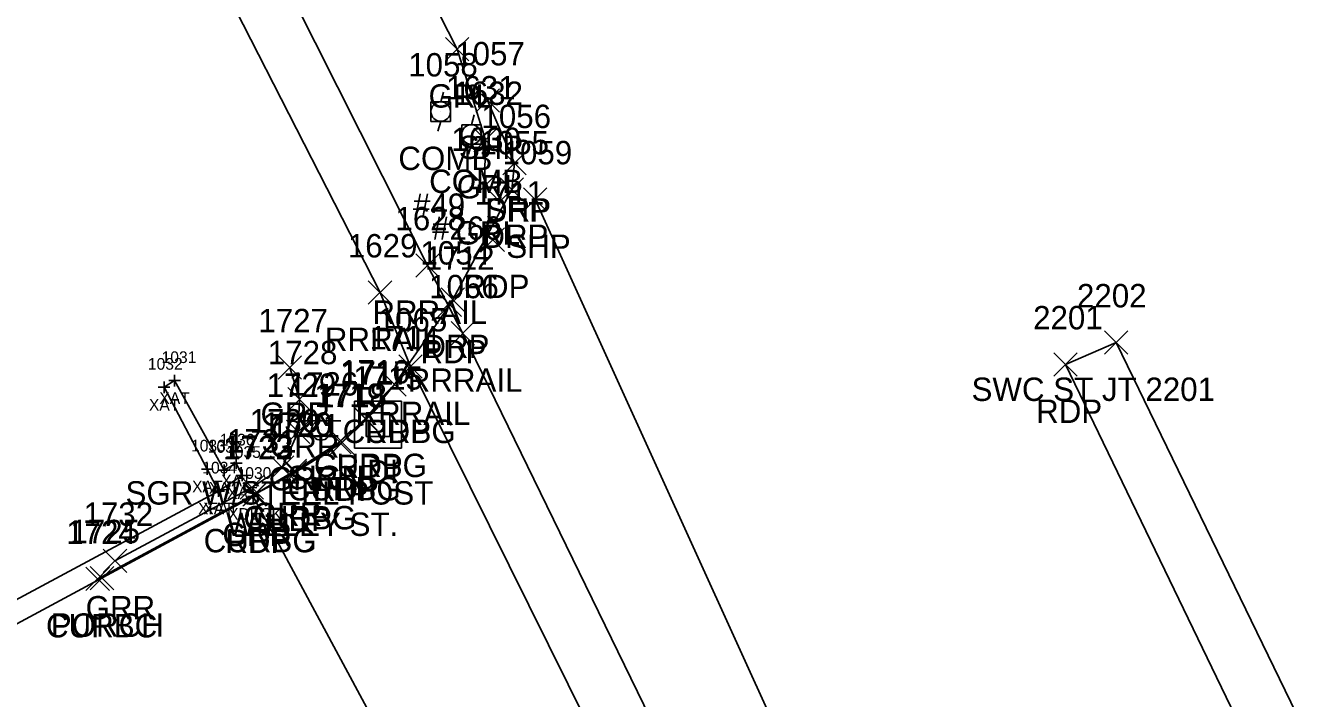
# Model space of a CAD drawing. Extents: x 1635588 to 1637550, y 621583 to 623638.
# Drawn here: x 1636369.1 to 1636479.5, y 623177.4 to 623234.9 of the extents above; entities that cross this region are included whole.
import ezdxf

# ---------------------------------------------------------------- set-up
doc = ezdxf.new("R2010")
doc.units = 0
for name, color, linetype in [('B_A', 7, 'Continuous'), ('B_I', 7, 'Continuous'), ('B_TIC', 7, 'Continuous'), ('BELB', 7, 'Continuous'), ('BF', 7, 'Continuous'), ('BSUBM', 7, 'Continuous'), ('D_A', 7, 'Continuous'), ('D_I', 7, 'Continuous'), ('DS', 7, 'Continuous'), ('L_A', 7, 'Continuous'), ('L_I', 7, 'Continuous'), ('L_TIC', 7, 'Continuous'), ('P_A', 7, 'Continuous'), ('P_I', 7, 'Continuous'), ('P_TIC', 7, 'Continuous'), ('PET', 7, 'Continuous'), ('PSP', 7, 'Continuous'), ('R_A', 7, 'Continuous'), ('R_C', 7, 'Continuous'), ('R_I', 7, 'Continuous'), ('R_TIC', 7, 'Continuous'), ('RC', 7, 'Continuous'), ('RDP', 7, 'Continuous'), ('RGR', 7, 'Continuous'), ('RR', 7, 'Continuous'), ('RSW', 7, 'Continuous'), ('S_A', 7, 'Continuous'), ('S_C', 7, 'Continuous'), ('S_I', 7, 'Continuous'), ('SSGN', 7, 'Continuous'), ('U_A', 7, 'Continuous'), ('U_C', 7, 'Continuous'), ('U_I', 7, 'Continuous'), ('UP', 7, 'Continuous')]:
    doc.layers.add(name, color=color, linetype=linetype)

msp = doc.modelspace()

# ---------------------------------------------------------------- linework, layer by layer
at = {"layer": 'B_TIC'}
for p, q in [((1636380.9, 623204.01), (1636380.98, 623204.01)), ((1636381.79, 623204.58), (1636381.86, 623204.58)), ((1636384.59, 623197.02), (1636384.67, 623197.02)), ((1636387.07, 623197.53), (1636387.15, 623197.53)), ((1636386.02, 623196.91), (1636386.1, 623196.91)), ((1636387.58, 623196.47), (1636387.66, 623196.47)), ((1636385.55, 623195.14), (1636385.63, 623195.14)), ((1636385.55, 623195.14), (1636385.63, 623195.14)), ((1636388.52, 623194.68), (1636388.6, 623194.68))]:
    msp.add_line(p, q, dxfattribs=at)
for points in [[(1636381.79, 623204.08), (1636381.79, 623205.08)], [(1636380.4, 623204.01), (1636381.4, 623204.01)], [(1636380.9, 623203.51), (1636380.9, 623204.51)], [(1636381.29, 623204.58), (1636382.29, 623204.58)], [(1636384.09, 623197.02), (1636385.09, 623197.02)], [(1636384.59, 623196.52), (1636384.59, 623197.52)], [(1636386.02, 623196.41), (1636386.02, 623197.41)], [(1636386.57, 623197.53), (1636387.57, 623197.53)], [(1636387.07, 623197.03), (1636387.07, 623198.03)], [(1636385.52, 623196.91), (1636386.52, 623196.91)], [(1636387.08, 623196.47), (1636388.08, 623196.47)], [(1636387.58, 623195.97), (1636387.58, 623196.97)], [(1636385.05, 623195.14), (1636386.05, 623195.14)], [(1636385.05, 623195.14), (1636386.05, 623195.14)], [(1636385.55, 623194.64), (1636385.55, 623195.64)], [(1636385.55, 623194.64), (1636385.55, 623195.64)], [(1636388.52, 623194.18), (1636388.52, 623195.18)], [(1636388.02, 623194.68), (1636389.02, 623194.68)]]:
    msp.add_lwpolyline(points, dxfattribs=at)
at = {"layer": 'BELB'}
msp.add_lwpolyline([(1636339.78, 623132.09), (1636403.65, 623166.46), (1636403.69, 623166.44), (1636388.52, 623194.68), (1636325.04, 623160.46), (1636339.78, 623132.09)], dxfattribs=at)
at = {"layer": 'BF'}
msp.add_lwpolyline([(1636385.55, 623195.14), (1636325.61, 623162.96)], dxfattribs=at)
at = {"layer": 'BSUBM'}
msp.add_lwpolyline([(1636381.79, 623204.58), (1636380.9, 623204.01), (1636384.59, 623197.02), (1636385.55, 623195.14), (1636387.58, 623196.47), (1636387.07, 623197.53), (1636386.02, 623196.91), (1636381.79, 623204.58)], dxfattribs=at)
at = {"layer": 'DS'}
for p, q in [((1636397.18, 623202.81), (1636401.18, 623202.81)), ((1636397.18, 623198.81), (1636397.18, 623202.81)), ((1636401.18, 623202.81), (1636401.18, 623198.81)), ((1636398.18, 623199.81), (1636398.18, 623201.81)), ((1636398.18, 623201.81), (1636400.18, 623201.81)), ((1636400.18, 623201.81), (1636400.18, 623199.81)), ((1636399.18, 623200.81), (1636399.18, 623200.81)), ((1636399.18, 623200.81), (1636399.18, 623200.81)), ((1636400.18, 623199.81), (1636398.18, 623199.81)), ((1636401.18, 623198.81), (1636397.18, 623198.81))]:
    msp.add_line(p, q, dxfattribs=at)
at = {"layer": 'L_TIC'}
for points in [[(1636374.59, 623186.68), (1636376.59, 623188.68)], [(1636376.59, 623186.68), (1636374.59, 623188.68)]]:
    msp.add_lwpolyline(points, dxfattribs=at)
at = {"layer": 'P_TIC'}
for points in [[(1636407.55, 623227.53), (1636409.55, 623229.53)], [(1636409.55, 623227.53), (1636407.55, 623229.53)], [(1636409.84, 623222.17), (1636411.84, 623224.17)], [(1636411.84, 623222.17), (1636409.84, 623224.17)], [(1636411.61, 623219.07), (1636413.61, 623221.07)], [(1636413.61, 623219.07), (1636411.61, 623221.07)], [(1636407.99, 623215.63), (1636409.99, 623217.63)], [(1636409.99, 623215.63), (1636407.99, 623217.63)], [(1636404.31, 623210.06), (1636406.31, 623212.06)], [(1636406.31, 623210.06), (1636404.31, 623212.06)], [(1636456.94, 623204.96), (1636458.94, 623206.96)], [(1636458.94, 623204.96), (1636456.94, 623206.96)], [(1636399.58, 623203.24), (1636401.58, 623205.24)], [(1636401.58, 623203.24), (1636399.58, 623205.24)], [(1636397.16, 623200.24), (1636399.16, 623202.24)], [(1636399.16, 623200.24), (1636397.16, 623202.24)], [(1636395.12, 623198.3), (1636397.12, 623200.3)], [(1636397.12, 623198.3), (1636395.12, 623200.3)], [(1636391.11, 623195.72), (1636393.11, 623197.72)], [(1636393.11, 623195.72), (1636391.11, 623197.72)], [(1636387.63, 623193.84), (1636389.63, 623195.84)], [(1636389.63, 623193.84), (1636387.63, 623195.84)]]:
    msp.add_lwpolyline(points, dxfattribs=at)
at = {"layer": 'PET'}
for points in [[(1636457.94, 623205.96), (1636503.15, 623112.3), (1636505.74, 623110.41), (1636508.84, 623109.19), (1636510.58, 623108.45)], [(1636400.58, 623204.24), (1636398.16, 623201.24), (1636396.12, 623199.3), (1636392.11, 623196.72), (1636388.63, 623194.84)], [(1636388.63, 623194.84), (1636388.52, 623194.68)]]:
    msp.add_lwpolyline(points, dxfattribs=at)
at = {"layer": 'PSP'}
for points in [[(1636410.84, 623223.17), (1636408.55, 623228.53)], [(1636412.61, 623220.07), (1636436.6, 623167.3), (1636456.23, 623125.07), (1636460.67, 623115.98), (1636475.52, 623084.87), (1636494.51, 623045.42), (1636524.16, 622986.51), (1636530.74, 622972.24), (1636554.07, 622925.3), (1636577.18, 622886.3), (1636601.72, 622847.41), (1636613.46, 622830.09), (1636645.38, 622782.47), (1636700.61, 622698.86), (1636734.28, 622648.07), (1636752.12, 622619.3), (1636752.46, 622616.81), (1636755.34, 622613.42), (1636810.04, 622534.39), (1636855.63, 622465.66), (1636874.76, 622437.49), (1636904.15, 622393.55)]]:
    msp.add_lwpolyline(points, dxfattribs=at)
at = {"layer": 'R_TIC'}
for points in [[(1636404.95, 623231.92), (1636406.95, 623233.92)], [(1636406.95, 623231.92), (1636404.95, 623233.92)], [(1636407.36, 623224.15), (1636409.36, 623226.15)], [(1636409.36, 623224.15), (1636407.36, 623226.15)], [(1636409.84, 623222.17), (1636411.84, 623224.17)], [(1636411.84, 623222.17), (1636409.84, 623224.17)], [(1636407.27, 623220.21), (1636409.27, 623222.21)], [(1636409.27, 623220.21), (1636407.27, 623222.21)], [(1636409.61, 623219.92), (1636411.61, 623221.92)], [(1636411.61, 623219.92), (1636409.61, 623221.92)], [(1636402.41, 623213.43), (1636404.41, 623215.43)], [(1636404.41, 623213.43), (1636402.41, 623215.43)], [(1636398.35, 623211.11), (1636400.35, 623213.11)], [(1636400.35, 623211.11), (1636398.35, 623213.11)], [(1636404.57, 623210.5), (1636406.57, 623212.5)], [(1636406.57, 623210.5), (1636404.57, 623212.5)], [(1636405.43, 623207.62), (1636407.43, 623209.62)], [(1636407.43, 623207.62), (1636405.43, 623209.62)], [(1636461.26, 623206.84), (1636463.26, 623208.84)], [(1636463.26, 623206.84), (1636461.26, 623208.84)], [(1636390.65, 623204.71), (1636392.65, 623206.71)], [(1636392.65, 623204.71), (1636390.65, 623206.71)], [(1636400.96, 623204.78), (1636402.96, 623206.78)], [(1636402.96, 623204.78), (1636400.96, 623206.78)], [(1636399.58, 623203.24), (1636401.58, 623205.24)], [(1636401.58, 623203.24), (1636399.58, 623205.24)], [(1636391.46, 623201.98), (1636393.46, 623203.98)], [(1636393.46, 623201.98), (1636391.46, 623203.98)], [(1636397.12, 623200.33), (1636399.12, 623202.33)], [(1636399.12, 623200.33), (1636397.12, 623202.33)], [(1636391.36, 623199.19), (1636393.36, 623201.19)], [(1636393.36, 623199.19), (1636391.36, 623201.19)], [(1636394.88, 623198.33), (1636396.88, 623200.33)], [(1636396.88, 623198.33), (1636394.88, 623200.33)], [(1636389.98, 623196.14), (1636391.98, 623198.14)], [(1636391.98, 623196.14), (1636389.98, 623198.14)], [(1636391.08, 623195.86), (1636393.08, 623197.86)], [(1636393.08, 623195.86), (1636391.08, 623197.86)], [(1636387.39, 623194.43), (1636389.39, 623196.43)], [(1636389.39, 623194.43), (1636387.39, 623196.43)], [(1636387.7, 623193.9), (1636389.7, 623195.9)], [(1636389.7, 623193.9), (1636387.7, 623195.9)], [(1636387.7, 623193.9), (1636389.7, 623195.9)], [(1636389.7, 623193.9), (1636387.7, 623195.9)], [(1636375.7, 623188.16), (1636377.7, 623190.16)], [(1636377.7, 623188.16), (1636375.7, 623190.16)], [(1636374.22, 623186.62), (1636376.22, 623188.62)], [(1636376.22, 623186.62), (1636374.22, 623188.62)]]:
    msp.add_lwpolyline(points, dxfattribs=at)
at = {"layer": 'RC'}
for points in [[(1636400.58, 623204.24), (1636405.31, 623211.06)], [(1636400.58, 623204.24), (1636398.12, 623201.33), (1636395.88, 623199.33), (1636392.08, 623196.86), (1636388.7, 623194.9)], [(1636388.7, 623194.9), (1636375.22, 623187.62)]]:
    msp.add_lwpolyline(points, dxfattribs=at)
at = {"layer": 'RDP'}
for points in [[(1636405.57, 623211.5), (1636410.61, 623220.92), (1636410.84, 623223.17)], [(1636405.57, 623211.5), (1636405.31, 623211.06)]]:
    msp.add_lwpolyline(points, dxfattribs=at)
at = {"layer": 'RGR'}
for points in [[(1636408.27, 623221.21), (1636408.36, 623225.15), (1636405.95, 623232.92), (1636401.32, 623242.01), (1636384.07, 623275.37), (1636372.77, 623296.95), (1636350.97, 623335.65), (1636322.15, 623384), (1636305.19, 623409.8), (1636285.27, 623437.15)], [(1636391.65, 623205.71), (1636392.46, 623202.98), (1636392.36, 623200.19), (1636390.98, 623197.14), (1636388.39, 623195.43), (1636376.7, 623189.16)]]:
    msp.add_lwpolyline(points, dxfattribs=at)
at = {"layer": 'RR'}
for points in [[(1635804.38, 623587.78), (1635886, 623591.18), (1635924.86, 623590.87), (1635951.97, 623589.69), (1635990.42, 623585.12), (1636025.5, 623577.68), (1636061.16, 623567.3), (1636080.11, 623560.16), (1636116.76, 623544.58), (1636140.64, 623532.31), (1636172.21, 623513.66), (1636196.85, 623496.79), (1636223, 623476.01), (1636248.62, 623451.82), (1636277.3, 623421.48), (1636310.55, 623379.63), (1636333.74, 623345.07), (1636353.23, 623312.06), (1636372.67, 623275.5), (1636403.41, 623214.43)], [(1635804.54, 623582.78), (1635886.42, 623586.09), (1635924.26, 623585.89), (1635952.04, 623584.59), (1635989.32, 623580.18), (1636024.35, 623572.88), (1636059.67, 623562.36), (1636078.46, 623555.55), (1636114.37, 623540.19), (1636138.58, 623527.78), (1636169.41, 623509.57), (1636193.73, 623492.88), (1636219.9, 623472.06), (1636245.31, 623448.34), (1636273.58, 623418.05), (1636306.45, 623376.76), (1636329.74, 623342.31), (1636348.93, 623309.65), (1636368.15, 623273.24), (1636399.35, 623212.11)], [(1636406.43, 623208.62), (1636403.41, 623214.43)], [(1636401.96, 623205.78), (1636399.35, 623212.11)], [(1636406.43, 623208.62), (1636424.65, 623171.19), (1636442.27, 623131.47), (1636462.36, 623079.17), (1636475.1, 623045.34), (1636499.5, 622979.8), (1636509.41, 622950.55), (1636516.07, 622929.71), (1636530.2, 622882.11), (1636568.93, 622740.93), (1636580.62, 622697.82)], [(1636401.96, 623205.78), (1636420.49, 623168.36), (1636437.73, 623129.25), (1636458.96, 623074.5), (1636470.76, 623043.73), (1636495.27, 622977.34), (1636504.04, 622950.72), (1636511.18, 622928.71), (1636525.38, 622880.65), (1636564.25, 622739.19), (1636576, 622696.58)]]:
    msp.add_lwpolyline(points, dxfattribs=at)
at = {"layer": 'RSW'}
for points in [[(1636462.26, 623207.84), (1636457.94, 623205.96)], [(1636462.26, 623207.84), (1636507.51, 623114.66)]]:
    msp.add_lwpolyline(points, dxfattribs=at)
at = {"layer": 'SSGN'}
for p, q in [((1636392.66, 623201.15), (1636396, 623201.15)), ((1636394.31, 623200.32), (1636394.31, 623200.32))]:
    msp.add_line(p, q, dxfattribs=at)
msp.add_circle((1636394.31, 623200.32), 0.833, dxfattribs=at)
at = {"layer": 'UP'}
for p, q in [((1636404.79, 623229.24), (1636404.54, 623228.41)), ((1636403.7, 623226.74), (1636403.7, 623228.41)), ((1636403.7, 623228.41), (1636405.37, 623228.41)), ((1636405.37, 623228.41), (1636405.37, 623226.74)), ((1636404.54, 623227.58), (1636404.54, 623227.58)), ((1636407.41, 623227.29), (1636407.16, 623226.45)), ((1636405.37, 623226.74), (1636403.7, 623226.74)), ((1636404.29, 623225.91), (1636404.54, 623226.74)), ((1636406.33, 623224.79), (1636406.33, 623226.45)), ((1636406.33, 623226.45), (1636407.99, 623226.45)), ((1636407.99, 623226.45), (1636407.99, 623224.79)), ((1636407.99, 623224.79), (1636406.33, 623224.79)), ((1636406.91, 623223.95), (1636407.16, 623224.79)), ((1636407.16, 623225.62), (1636407.16, 623225.62))]:
    msp.add_line(p, q, dxfattribs=at)
for centre in [(1636404.54, 623227.58), (1636407.16, 623225.62)]:
    msp.add_circle(centre, 0.833, dxfattribs=at)

# ---------------------------------------------------------------- texts
at = {"layer": 'B_A'}
for s, p in [('XAT', (1636379.6, 623202.01)), ('XAT', (1636380.49, 623202.58)), ('XAT', (1636383.29, 623195.02)), ('XAT', (1636384.72, 623194.91)), ('XAT', (1636385.77, 623195.53)), ('XAT', (1636386.28, 623194.47)), ('XFAT', (1636383.8, 623193.14)), ('XAT', (1636384.25, 623193.14)), ('XDECK', (1636386.36, 623192.68))]:
    msp.add_text(s, height=1, dxfattribs=at).set_placement(p)
at = {"layer": 'B_I'}
for s, p in [('1031', (1636380.68, 623206.08)), ('1032', (1636379.51, 623205.51)), ('1033', (1636383.2, 623198.52)), ('1037', (1636384.63, 623198.41)), ('1036', (1636385.65, 623199.03)), ('1035', (1636386.19, 623197.97)), ('1034', (1636384.16, 623196.64)), ('1034', (1636384.16, 623196.64)), ('1030', (1636387.09, 623196.18))]:
    msp.add_text(s, height=1, dxfattribs=at).set_placement(p)
at = {"layer": 'D_A'}
msp.add_text('DI', height=2, dxfattribs=at).set_placement((1636398.24, 623195.81))
at = {"layer": 'D_I'}
msp.add_text('1715', height=2, dxfattribs=at).set_placement((1636397.06, 623203.81))
at = {"layer": 'L_A'}
msp.add_text('PORCH', height=2, dxfattribs=at).set_placement((1636371.21, 623182.68))
at = {"layer": 'L_I'}
msp.add_text('1725', height=2, dxfattribs=at).set_placement((1636372.89, 623190.68))
at = {"layer": 'P_A'}
for s, p in [('SHP', (1636406.09, 623223.53)), ('SHP', (1636408.38, 623218.17)), ('SHP', (1636410.15, 623215.07)), ('RDP', (1636406.48, 623211.63)), ('RDP', (1636402.8, 623206.06)), ('RDP', (1636455.43, 623200.96)), ('RDP', (1636398.06, 623199.24)), ('RDP', (1636395.65, 623196.24)), ('RDP', (1636393.61, 623194.3)), ('RDP', (1636389.6, 623191.72)), ('RDP', (1636386.12, 623189.84))]:
    msp.add_text(s, height=2, dxfattribs=at).set_placement(p)
at = {"layer": 'P_I'}
for s, p in [('1057', (1636405.78, 623231.53)), ('1056', (1636408.02, 623226.17)), ('1059', (1636409.83, 623223.07)), ('1711', (1636407.43, 623219.63)), ('1712', (1636403.19, 623214.06)), ('2201', (1636455.17, 623208.96)), ('1714', (1636398.45, 623207.24)), ('1717', (1636396.03, 623204.24)), ('1718', (1636393.99, 623202.3)), ('1721', (1636389.98, 623199.72)), ('1722', (1636385.94, 623197.84))]:
    msp.add_text(s, height=2, dxfattribs=at).set_placement(p)
at = {"layer": 'R_A'}
for s, p in [('GRL', (1636403.5, 623227.92)), ('GRL', (1636405.91, 623220.15)), ('DRP', (1636408.33, 623218.17)), ('GRL', (1636405.81, 623216.21)), ('DRP', (1636408.1, 623215.92)), ('RRRAIL', (1636398.7, 623209.43)), ('RRRAIL', (1636394.64, 623207.11)), ('DRP', (1636403.06, 623206.5)), ('RRRAIL', (1636401.72, 623203.62)), ('SWC ST JT 2201', (1636449.91, 623202.84)), ('GRR', (1636389.14, 623200.71)), ('RRRAIL', (1636397.26, 623200.78)), ('CURBG', (1636396.16, 623199.24)), ('GRR', (1636389.94, 623197.98)), ('CURBG', (1636393.7, 623196.33)), ('GRR', (1636389.85, 623195.19)), ('CURBG', (1636391.46, 623194.33)), ('CURBG', (1636387.67, 623191.86)), ('GRR', (1636388.47, 623192.14)), ('CURBG', (1636384.28, 623189.9)), ('CURBC', (1636384.28, 623189.9)), ('GRR', (1636385.88, 623190.43)), ('GRR', (1636374.19, 623184.16)), ('CURBC', (1636370.8, 623182.62))]:
    msp.add_text(s, height=2, dxfattribs=at).set_placement(p)
at = {"layer": 'R_C'}
msp.add_text('SGR W/STEEL POST', height=2, dxfattribs=at).set_placement((1636377.6, 623193.98))
at = {"layer": 'R_I'}
for s, p in [('1632', (1636405.62, 623228.15)), ('1056', (1636408.02, 623226.17)), ('1630', (1636405.44, 623224.21)), ('1055', (1636407.84, 623223.92)), ('1628', (1636400.67, 623217.43)), ('1629', (1636396.6, 623215.11)), ('1054', (1636402.8, 623214.5)), ('1066', (1636403.55, 623211.62)), ('2202', (1636458.92, 623210.84)), ('1727', (1636388.95, 623208.71)), ('1065', (1636399.15, 623208.78)), ('1714', (1636398.45, 623207.24)), ('1728', (1636389.76, 623205.98)), ('1716', (1636395.94, 623204.33)), ('1729', (1636389.66, 623203.19)), ('1719', (1636393.75, 623202.33)), ('1730', (1636388.2, 623200.14)), ('1720', (1636389.31, 623199.86)), ('1731', (1636386.27, 623198.43)), ('1723', (1636386.01, 623197.9)), ('1723', (1636386.01, 623197.9)), ('1732', (1636374.01, 623192.16)), ('1724', (1636372.53, 623190.62))]:
    msp.add_text(s, height=2, dxfattribs=at).set_placement(p)
at = {"layer": 'S_A'}
msp.add_text('SIGN', height=2, dxfattribs=at).set_placement((1636391.45, 623195.3))
at = {"layer": 'S_C'}
msp.add_text('WILLEY ST.', height=2, dxfattribs=at).set_placement((1636386.2, 623191.3))
at = {"layer": 'S_I'}
msp.add_text('1726', height=2, dxfattribs=at).set_placement((1636391.54, 623203.3))
at = {"layer": 'U_A'}
for p in [(1636400.92, 623222.58), (1636403.55, 623220.62)]:
    msp.add_text('COMB', height=2, dxfattribs=at).set_placement(p)
at = {"layer": 'U_C'}
for s, p in [('#49', (1636402.17, 623218.58)), ('#266', (1636403.8, 623216.62))]:
    msp.add_text(s, height=2, dxfattribs=at).set_placement(p)
at = {"layer": 'U_I'}
for s, p in [('1058', (1636401.76, 623230.58)), ('1631', (1636404.99, 623228.62))]:
    msp.add_text(s, height=2, dxfattribs=at).set_placement(p)

doc.saveas('drawing.dxf')
